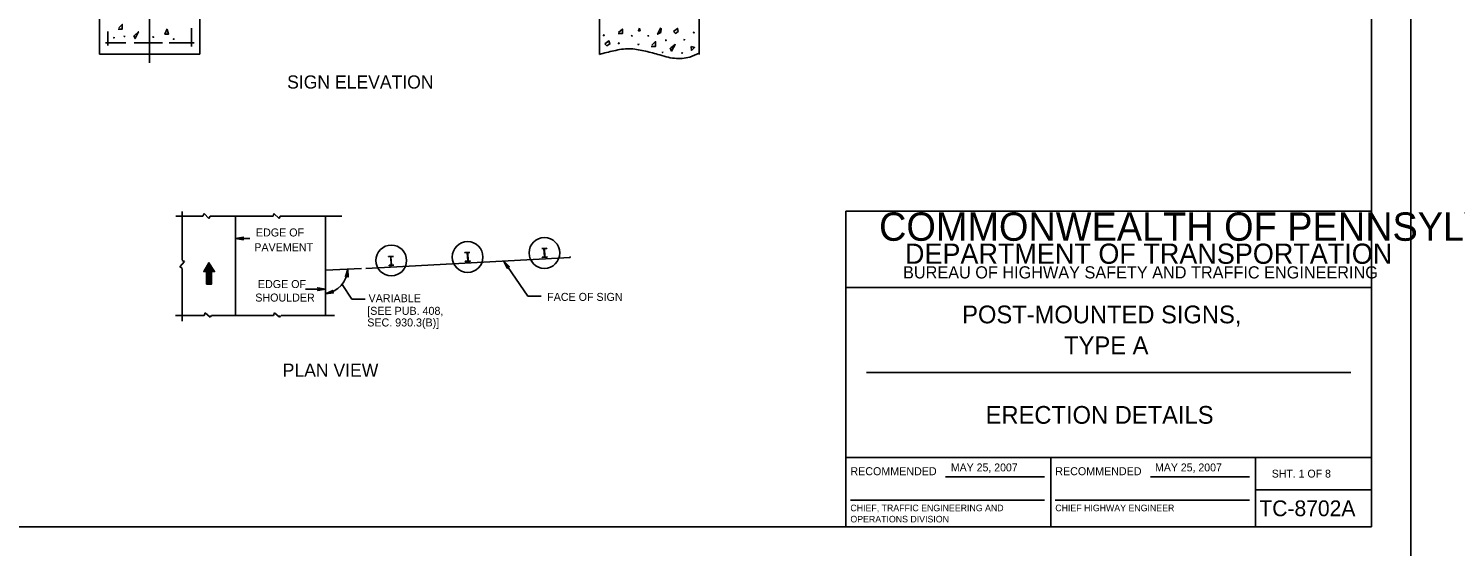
# Model space of a CAD drawing. Extents: x 637580 to 641008, y 294594 to 295782.
# Drawn here: x 637895 to 638438, y 295195 to 295392 of the extents above; entities that cross this region are included whole.
import ezdxf

# ---------------------------------------------------------------- set-up
doc = ezdxf.new("R2010")
doc.units = 0
for name, color, linetype in [('1', 7, 'Continuous'), ('2', 7, 'Continuous'), ('3', 7, 'Continuous'), ('PLT-BNDY', 7, 'Continuous')]:
    doc.layers.add(name, color=color, linetype=linetype)

# ---------------------------------------------------------------- blocks, each defined once
blk = doc.blocks.new('RARROW')
at = {"layer": '3'}
blk.add_lwpolyline([(-2.2695, 0.285), (-2.184875, 0.12075), (0, 0), (-2.2695, 0.285), (-2.38575, 0.384625), (0, 0), (-2.183125, -0.108), (-2.262875, -0.2705), (0, 0), (-2.38575, -0.379125), (-2.262875, -0.2705)], dxfattribs=at)

msp = doc.modelspace()

# ---------------------------------------------------------------- linework, layer by layer
at = {"layer": '1'}
for p, q in [((638406.31, 295202.63), (638406.31, 295766.63)), ((638206.31, 295202.63), (638206.31, 295322.63)), ((638206.31, 295322.63), (638406.31, 295322.63)), ((638406.31, 295293.63), (638206.31, 295293.63)), ((638214.06, 295261.31), (638398.56, 295261.31)), ((638206.31, 295229), (638406.31, 295229)), ((638284.31, 295229), (638284.31, 295202.63)), ((638362.19, 295202.63), (638362.19, 295229)), ((638244.24, 295221.57), (638281.87, 295221.57)), ((638322.24, 295221.57), (638359.87, 295221.57)), ((638362.19, 295216.63), (638406.31, 295216.63)), ((638207.99, 295212.68), (638281.87, 295212.68)), ((638285.99, 295212.68), (638359.87, 295212.68)), ((638406.31, 295202.63), (637620.31, 295202.63)), ((637620.31, 295202.63), (638206.31, 295202.63))]:
    msp.add_line(p, q, dxfattribs=at)
for points in [[(637962.81, 295294.88), (637962.81, 295299.63), (637961.81, 295299.63), (637963.81, 295303), (637965.94, 295299.63), (637964.81, 295299.63), (637964.81, 295294.88), (637962.81, 295294.88)], [(637963.06, 295294.88), (637963.06, 295299.75), (637962.19, 295299.75), (637963.81, 295302.38), (637965.44, 295299.75), (637964.69, 295299.75), (637964.69, 295294.88), (637963.19, 295294.88), (637963.19, 295300.25), (637962.69, 295300), (637963.81, 295301.88), (637965.06, 295300), (637964.31, 295300.25), (637964.31, 295295.25), (637963.44, 295295.25), (637963.44, 295300.5), (637963.81, 295301.13), (637964.31, 295300.5), (637963.81, 295300.5), (637963.81, 295295.38)], [(637963.06, 295294.88), (637962.81, 295294.88)]]:
    msp.add_lwpolyline(points, dxfattribs=at)
at = {"layer": '2'}
for p, q in [((637941.19, 295463.25), (637941.19, 295379)), ((637922.19, 295454.75), (637922.19, 295382.38)), ((637960.31, 295454.13), (637960.31, 295382.38)), ((638112.44, 295420), (638112.44, 295382.25)), ((638150.44, 295409.25), (638150.44, 295382.25)), ((637925.31, 295391), (637925.31, 295385.63)), ((637957.19, 295392.25), (637957.19, 295385.25)), ((637932.19, 295386.63), (637924.44, 295386.63)), ((637946.06, 295386.63), (637935.31, 295386.63)), ((637958.19, 295386.63), (637948.69, 295386.63)), ((637960.31, 295382.38), (637922.19, 295382.38)), ((637961.44, 295320.75), (637951.19, 295320.75)), ((637953.56, 295304), (637953.56, 295322.5)), ((637961.44, 295320.75), (637961.94, 295321.75)), ((637961.94, 295321.75), (637963.81, 295319.88)), ((637963.81, 295319.88), (637964.31, 295320.75)), ((637988.19, 295320.75), (637964.31, 295320.75)), ((637973.94, 295283.25), (637973.94, 295320.75)), ((637988.19, 295320.75), (637988.56, 295321.75)), ((637988.56, 295321.75), (637990.56, 295319.88)), ((637990.56, 295319.88), (637990.94, 295320.75)), ((638014.44, 295320.75), (637990.94, 295320.75)), ((638008.19, 295283.25), (638008.19, 295320.75)), ((637979.31, 295312.25), (637973.94, 295312.25)), ((638092.44, 295308.5), (638090.56, 295308.38)), ((638090.56, 295308.38), (638090.56, 295308.38)), ((638091.31, 295308.38), (638090.56, 295308.38)), ((638091.31, 295308.38), (638091.56, 295305.25)), ((638091.56, 295308.38), (638091.69, 295305.25)), ((638092.44, 295308.38), (638091.56, 295308.38)), ((638092.44, 295308.5), (638092.44, 295308.38)), ((637952.69, 295301.5), (637954.44, 295303.5)), ((637954.44, 295303.5), (637953.56, 295303.88)), ((638023.56, 295300.88), (638101.31, 295305)), ((638034.06, 295305.38), (638032.19, 295305.38)), ((638032.19, 295305.38), (638032.19, 295305.25)), ((638033.06, 295305.38), (638032.19, 295305.25)), ((638033.06, 295305.25), (638033.19, 295302.13)), ((638033.06, 295305.25), (638033.31, 295302.13)), ((638034.06, 295305.38), (638033.19, 295305.38)), ((638033.19, 295303.75), (638033.19, 295303.75)), ((638034.06, 295305.38), (638034.06, 295305.38)), ((638063.06, 295306.88), (638061.19, 295306.88)), ((638061.19, 295306.88), (638061.19, 295306.75)), ((638062.06, 295306.88), (638061.19, 295306.75)), ((638061.31, 295303.63), (638061.31, 295303.5)), ((638062.31, 295303.63), (638061.31, 295303.63)), ((638063.19, 295303.5), (638061.31, 295303.5)), ((638062.06, 295306.75), (638062.31, 295303.75)), ((638063.06, 295306.88), (638062.31, 295306.88)), ((638062.31, 295306.75), (638062.44, 295303.75)), ((638062.31, 295305.25), (638062.31, 295305.25)), ((638063.19, 295303.75), (638062.44, 295303.63)), ((638063.06, 295306.88), (638063.06, 295306.88)), ((638063.19, 295303.75), (638063.19, 295303.5)), ((638085.19, 295290.25), (638076.08, 295303.66)), ((638092.56, 295305.13), (638090.69, 295305)), ((638090.69, 295305.13), (638090.69, 295305)), ((638091.56, 295305.13), (638090.69, 295305.13)), ((638091.56, 295306.75), (638091.56, 295306.75)), ((638092.56, 295305.25), (638091.69, 295305.13)), ((638092.56, 295305.25), (638092.56, 295305.13)), ((638101.31, 295305), (638101.31, 295305.38)), ((637953.56, 295301), (637952.69, 295301.5)), ((637953.56, 295280.75), (637953.56, 295300.88)), ((638008.19, 295300.17), (638021.81, 295300.88)), ((638034.19, 295302.13), (638032.44, 295301.88)), ((638032.44, 295302.13), (638032.44, 295301.88)), ((638033.19, 295302.13), (638032.44, 295302.13)), ((638034.19, 295302.13), (638033.31, 295302.13)), ((638034.19, 295302.13), (638034.19, 295302.13)), ((638008.19, 295293), (638000.56, 295293)), ((638018.19, 295289.13), (638014.45, 295294.73)), ((638023.31, 295289.13), (638018.19, 295289.13)), ((638090.31, 295290.25), (638085.19, 295290.25)), ((637961.94, 295283), (637951.06, 295283)), ((637961.94, 295283), (637962.31, 295284)), ((637962.31, 295284), (637964.31, 295282.25)), ((637964.31, 295282.25), (637964.81, 295283)), ((637988.31, 295283), (637964.81, 295283)), ((637988.31, 295283), (637988.81, 295284)), ((637988.81, 295284), (637990.69, 295282.25)), ((637990.69, 295282.25), (637991.06, 295283)), ((638011.56, 295283), (637991.31, 295283))]:
    msp.add_line(p, q, dxfattribs=at)
for points in [[(637929.44, 295392.38), (637930.81, 295393.63), (637930.81, 295391.88), (637929.19, 295391.88)], [(637935.44, 295389.38), (637936.94, 295390.88), (637935.69, 295388.25), (637935.19, 295389.38)], [(637947.94, 295392), (637947.06, 295389.88), (637948.44, 295389.88), (637947.94, 295391.75)], [(638114.19, 295389.75), (638113.94, 295389.38), (638114.19, 295389.38), (638114.19, 295389.63)], [(638119.69, 295390.63), (638121.19, 295391.88), (638121.19, 295390.13), (638119.56, 295390.13)], [(638127.69, 295392.25), (638127.31, 295391.25), (638127.94, 295391.25), (638127.69, 295392.25)], [(638135.81, 295392.38), (638134.56, 295389.88), (638135.81, 295390.63), (638135.94, 295392.13)], [(638140.69, 295391), (638142.19, 295392.13), (638142.44, 295391), (638141.44, 295390.25), (638140.69, 295391)], [(638148.44, 295390.88), (638148.31, 295390.5), (638148.56, 295390.5), (638148.44, 295390.75)], [(637927.69, 295388.75), (637927.56, 295388.5), (637927.69, 295388.5), (637927.69, 295388.75)], [(637931.69, 295389.25), (637931.56, 295389), (637931.69, 295389), (637931.69, 295389.25)], [(637942.56, 295389), (637942.44, 295388.75), (637942.69, 295388.75), (637942.56, 295389)], [(637950.44, 295388.25), (637950.19, 295388), (637950.44, 295388), (637950.44, 295388.25)], [(638114.56, 295386.25), (638116.06, 295387.38), (638116.44, 295386.25), (638115.31, 295385.5), (638114.56, 295386.25)], [(638119.94, 295386.75), (638119.69, 295386.38), (638119.94, 295386.38), (638119.94, 295386.63)], [(638124.81, 295389.5), (638124.69, 295389.25), (638124.94, 295389.25), (638124.81, 295389.38)], [(638127.31, 295386.25), (638127.19, 295386), (638127.44, 295386), (638127.31, 295386.25)], [(638131.06, 295389.5), (638130.94, 295389.25), (638131.19, 295389.25), (638131.06, 295389.38)], [(638132.44, 295385.75), (638133.81, 295387.13), (638133.81, 295385.25), (638132.19, 295385.25)], [(638137.81, 295387.88), (638137.69, 295387.5), (638137.81, 295387.5), (638137.81, 295387.75)], [(638139.69, 295384.75), (638141.31, 295386), (638139.94, 295383.5), (638139.44, 295384.75)], [(638144.81, 295388), (638144.69, 295387.75), (638144.81, 295387.75), (638144.81, 295388)], [(638147.31, 295385.25), (638147.56, 295383.75), (638148.69, 295384.88), (638147.31, 295385.25)], [(638136.44, 295383.25), (638136.44, 295383), (638136.56, 295383), (638136.44, 295383.25)], [(638143.94, 295383), (638143.81, 295382.75), (638144.06, 295382.75), (638143.94, 295383)]]:
    msp.add_lwpolyline(points, dxfattribs=at)
for centre, major_axis in [((638033.2, 295303.87), (0, 5.85)), ((638062.27, 295305.19), (0, 5.86)), ((638091.51, 295306.74), (0, 5.87))]:
    msp.add_ellipse(centre, major_axis=major_axis, ratio=0.996388, dxfattribs=at)
for centre, major_axis, start_param, end_param in [((638091.34, 295308.28), (0, 0.0425), 4.764749, 6.335545), ((638091.53, 295308.29), (0, -0.0425), 3.193953, 4.764749), ((638033.02, 295305.21), (0, 0.0425), 4.764749, 6.335545), ((638033.21, 295305.22), (0, -0.0425), 3.193953, 4.764749), ((638062.1, 295306.74), (0, 0.0425), 4.764749, 6.335545), ((638062.29, 295306.75), (0, -0.0425), 3.193953, 4.764749), ((638062.26, 295303.64), (0, 0.0425), 3.193953, 4.764749), ((638062.45, 295303.65), (0, -0.0425), 4.764749, 6.335545), ((638091.5, 295305.18), (0, 0.0425), 3.193953, 4.764749), ((638091.69, 295305.19), (0, -0.0425), 4.764749, 6.335545), ((638006.74, 295301.09), (0, 10.02), 3.286984, 4.664623), ((638033.18, 295302.1), (0, 0.0425), 3.193953, 4.764749), ((638033.37, 295302.11), (0, -0.0425), 4.764749, 6.335545)]:
    msp.add_ellipse(centre, major_axis=major_axis, ratio=0.996388, start_param=start_param, end_param=end_param, dxfattribs=at)
msp.add_spline([(638112.44, 295382.25), (638117.94, 295383.63), (638123.81, 295384.38), (638129.31, 295383.63), (638134.69, 295382.25), (638141.06, 295380.75), (638146.81, 295381.25), (638150.44, 295382.75)], degree=3, dxfattribs=at)
at = {"layer": 'PLT-BNDY'}
for points in [[(637580.31, 295781.63), (638421.31, 295781.63), (638421.31, 295187.63), (637580.31, 295187.63)], [(638421.31, 295781.63), (639262.31, 295781.63), (639262.31, 295187.63), (638421.31, 295187.63)]]:
    msp.add_lwpolyline(points, close=True, dxfattribs=at)

# ---------------------------------------------------------------- block references
at = {"layer": '2'}
for p, xscale, yscale, rotation in [((637973.94, 295312.25), 1.2574347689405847, 1.3092961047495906, 180), ((638076.08, 295303.66), 1.2574347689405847, 1.3092961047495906, 124.22439394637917), ((638016.71, 295300.61), 1.257434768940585, 1.3092961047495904, 81.17190166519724), ((638008.19, 295291.18), 1.2574347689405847, 1.3092961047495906, -163.35438489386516)]:
    msp.add_blockref('RARROW', p, dxfattribs=dict(at, xscale=xscale, yscale=yscale, rotation=rotation))
at = {"layer": '2', "xscale": 1.2574347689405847, "yscale": 1.3092961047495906}
msp.add_blockref('RARROW', (638008.19, 295293), dxfattribs=at)

# ---------------------------------------------------------------- texts
at = {"layer": '1'}
for s, height, p in [('COMMONWEALTH OF PENNSYLVANIA', 10.7828, (638218.9, 295311.36)), ('DEPARTMENT OF TRANSPORTATION', 7.6837, (638228.76, 295302.61)), ('BUREAU OF HIGHWAY SAFETY AND TRAFFIC ENGINEERING', 4.6253, (638228.04, 295297.04)), ('VARIABLE ', 3.043, (638024.56, 295288)), ('POST-MOUNTED SIGNS,', 6.75, (638250.54, 295279.97)), ('TYPE A', 6.75, (638289.35, 295268.22)), ('ERECTION DETAILS', 6.75, (638259.47, 295241.78)), ('RECOMMENDED', 3.048, (638207.99, 295222.2)), ('RECOMMENDED', 3.048, (638285.99, 295222.2)), ('SHT. 1 OF 8', 3, (638368.4, 295221.31)), ('CHIEF, TRAFFIC ENGINEERING AND', 2.5, (638207.99, 295208.51)), ('CHIEF HIGHWAY ENGINEER', 2.5, (638285.99, 295208.51)), ('TC-8702A', 6, (638363.68, 295206.63)), ('OPERATIONS DIVISION', 2.5, (638207.99, 295204.26))]:
    msp.add_text(s, height=height, dxfattribs=at).set_placement(p)
at = {"layer": '2'}
for s, height, p in [('SIGN ELEVATION', 5, (637993.56, 295369.25)), ('PLAN VIEW', 5, (637991.88, 295259.65)), ('MAY 25, 2007', 3, (638246.25, 295223.67)), ('MAY 25, 2007', 3, (638323.97, 295223.67))]:
    msp.add_text(s, height=height, dxfattribs=at).set_placement(p)
at = {"layer": '3'}
for s, height, p in [('EDGE OF', 3.044, (637981.69, 295313)), ('PAVEMENT', 3.043, (637981.06, 295307.38)), ('EDGE OF', 3.044, (637982.44, 295293.38)), ('SHOULDER', 3.043, (637981.44, 295288.25)), ('[SEE PUB. 408,', 3.0465, (638024.06, 295283.2)), ('FACE OF SIGN', 3.0427, (638092.56, 295288.5)), ('SEC. 930.3(B)]', 3.0465, (638024.06, 295278.78))]:
    msp.add_text(s, height=height, dxfattribs=at).set_placement(p)

doc.saveas('drawing.dxf')
